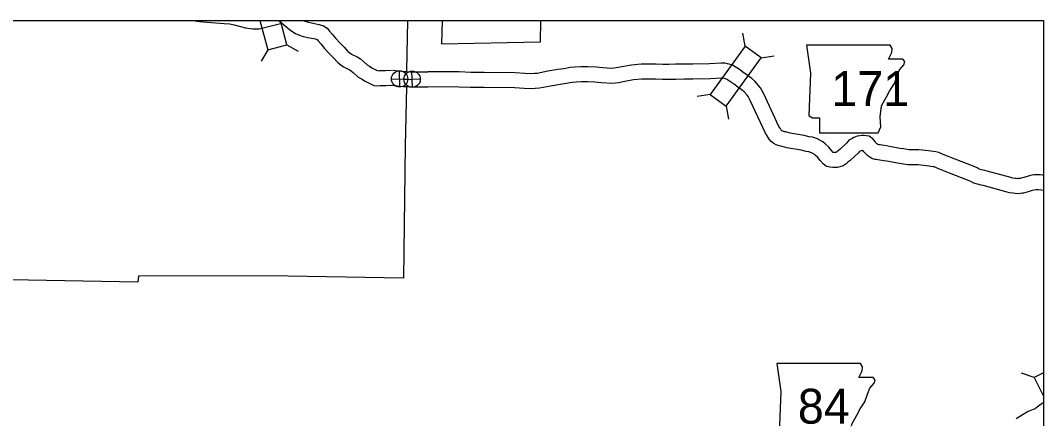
# Model space of a CAD drawing. Extents: x 1373862 to 1377080, y 1164775 to 1170415.
# Drawn here: x 1374409.6 to 1374613.9, y 1170309.3 to 1170388.8 of the extents above; entities that cross this region are included whole.
import ezdxf

# ---------------------------------------------------------------- set-up
doc = ezdxf.new("R2010")
doc.units = 0
doc.layers.add('1', color=7, linetype='Continuous')
doc.layers.add('Default', color=7, linetype='Continuous')

msp = doc.modelspace()

# ---------------------------------------------------------------- linework, layer by layer
at = {"layer": '1'}
msp.add_lwpolyline([(1373884.49, 1170388.77), (1374613.88, 1170388.77), (1374613.88, 1169861.94), (1373884.49, 1169861.94)], close=True, dxfattribs=at)
at = {"layer": 'Default'}
for p, q in [((1374554.29, 1170383.62), (1374553.87, 1170386.22)), ((1374459, 1170382.92), (1374457.68, 1170380.63)), ((1374462.83, 1170383.93), (1374465.11, 1170382.61)), ((1374557.5, 1170381.3), (1374560.11, 1170381.72)), ((1374485.38, 1170375.46), (1374485.3, 1170378.71)), ((1374487.88, 1170375.41), (1374487.8, 1170378.67)), ((1374483.71, 1170377.05), (1374486.97, 1170377.12)), ((1374486.21, 1170377), (1374489.47, 1170377.08)), ((1374547.34, 1170373.98), (1374544.73, 1170373.56)), ((1374550.55, 1170371.67), (1374550.97, 1170369.06)), ((1374612.02, 1170317.49), (1374609.51, 1170318.32)), ((1374613.88, 1170318.43), (1374612.02, 1170317.49)), ((1374612.02, 1170317.49), (1374613.88, 1170313.77))]:
    msp.add_line(p, q, dxfattribs=at)
for points in [[(1374443.92, 1170388.77), (1374444.08, 1170388.74), (1374445.42, 1170388.58), (1374447.72, 1170388.35), (1374450.32, 1170388.17), (1374451.45, 1170388.09), (1374452.33, 1170387.91), (1374453.55, 1170387.59), (1374454.54, 1170387.3), (1374455.98, 1170387.1)], [(1374457.45, 1170388.77), (1374459, 1170382.92), (1374462.83, 1170383.93), (1374461.55, 1170388.77)], [(1374461.16, 1170388.77), (1374461.49, 1170388.52), (1374462.4, 1170387.76), (1374463.44, 1170386.9), (1374464.58, 1170386.16), (1374465.37, 1170385.82), (1374466.11, 1170385.58), (1374467.38, 1170385.32), (1374468.53, 1170385.08), (1374468.83, 1170384.99), (1374468.85, 1170384.97), (1374469.07, 1170384.72), (1374469.58, 1170384.08), (1374470.35, 1170383.19), (1374471.3, 1170382.2), (1374472.06, 1170381.39), (1374472.99, 1170380.36), (1374473.61, 1170379.89), (1374474.15, 1170379.5), (1374475.45, 1170378.84), (1374475.75, 1170378.67), (1374476.07, 1170378.38), (1374477.07, 1170377.43), (1374477.84, 1170377.03), (1374478.34, 1170376.73), (1374479.42, 1170376.15), (1374480.18, 1170375.81), (1374480.99, 1170375.73), (1374481.45, 1170375.77), (1374482.61, 1170375.79), (1374483.79, 1170375.82)], [(1374466.1, 1170388.77), (1374466.42, 1170388.64), (1374466.89, 1170388.49), (1374467.99, 1170388.26), (1374469.3, 1170387.99), (1374470.17, 1170387.71), (1374470.87, 1170387.22), (1374471.37, 1170386.64), (1374471.89, 1170386), (1374472.57, 1170385.22), (1374473.48, 1170384.26), (1374474.26, 1170383.42), (1374475.03, 1170382.58), (1374475.41, 1170382.3), (1374475.72, 1170382.07), (1374476.89, 1170381.48), (1374477.52, 1170381.11), (1374478.1, 1170380.59), (1374478.84, 1170379.89), (1374479.3, 1170379.64), (1374479.81, 1170379.34), (1374480.75, 1170378.84), (1374480.96, 1170378.75), (1374481.02, 1170378.74), (1374481.31, 1170378.76), (1374482.55, 1170378.79), (1374483.73, 1170378.81)], [(1374486.93, 1170388.77), (1374486.74, 1170378.69)], [(1374493.81, 1170388.77), (1374493.69, 1170384.11), (1374513.44, 1170384.47), (1374513.55, 1170388.77)], [(1374455.98, 1170387.1), (1374455.98, 1170387.1), (1374456.67, 1170387.08), (1374457.32, 1170387.12), (1374458.6, 1170387.4), (1374460.25, 1170387.84), (1374461.85, 1170388.23)], [(1374483.92, 1170378.81), (1374485.11, 1170378.68), (1374486.29, 1170378.59), (1374486.79, 1170378.57)], [(1374486.87, 1170378.57), (1374487.42, 1170378.54), (1374488.49, 1170378.54), (1374489.72, 1170378.54), (1374491, 1170378.53)], [(1374522.88, 1170379.52), (1374521.48, 1170379.51), (1374520.31, 1170379.43), (1374519.41, 1170379.35), (1374518.14, 1170379.14), (1374516.92, 1170378.96), (1374514.95, 1170378.63), (1374512.81, 1170378.2), (1374512.26, 1170378.15), (1374511.7, 1170378.14), (1374510.32, 1170378.19), (1374508.38, 1170378.32), (1374502.19, 1170378.37), (1374500.66, 1170378.35), (1374499.55, 1170378.4), (1374497.24, 1170378.48), (1374490.99, 1170378.53)], [(1374596.23, 1170361.06), (1374594.19, 1170361.89), (1374593.68, 1170362.08), (1374592.98, 1170362.4), (1374592.41, 1170362.53), (1374590.9, 1170362.73), (1374588.98, 1170362.93), (1374587.01, 1170362.95), (1374585.95, 1170363.1), (1374585.2, 1170363.22), (1374584.19, 1170363.41), (1374583.11, 1170363.6), (1374582.5, 1170363.71), (1374581.68, 1170363.85), (1374581.27, 1170363.91), (1374581.04, 1170363.95), (1374580.84, 1170363.98), (1374580.8, 1170363.99), (1374580.77, 1170364.02), (1374580.63, 1170364.14), (1374580.48, 1170364.29), (1374580.37, 1170364.4), (1374580.25, 1170364.62), (1374579.83, 1170365.1), (1374579.09, 1170365.65), (1374578.57, 1170365.74), (1374578.07, 1170365.78), (1374577.66, 1170365.77), (1374577.18, 1170365.72), (1374576.7, 1170365.67), (1374576.37, 1170365.53), (1374576.04, 1170365.42), (1374575.66, 1170365.2), (1374575, 1170364.84), (1374574.64, 1170364.31), (1374573.31, 1170363.07), (1374572.93, 1170362.79), (1374572.62, 1170362.52), (1374572.55, 1170362.47), (1374572.43, 1170362.43), (1374572.3, 1170362.4), (1374572.11, 1170362.39), (1374571.94, 1170362.38), (1374571.91, 1170362.39), (1374571.58, 1170362.77), (1374571.01, 1170363.44), (1374570.28, 1170364.13), (1374569.79, 1170364.54), (1374568.77, 1170365.12), (1374567.73, 1170365.45), (1374567.08, 1170365.55), (1374566.12, 1170365.78), (1374563.27, 1170366.28), (1374562.42, 1170366.51), (1374562.19, 1170366.56), (1374561.95, 1170366.62), (1374561.71, 1170366.7), (1374561.65, 1170366.73), (1374561.59, 1170366.78), (1374561.5, 1170366.88), (1374561.28, 1170367.23), (1374561.06, 1170367.62), (1374558.04, 1170374.11), (1374557.66, 1170374.82), (1374557.36, 1170375.33), (1374556.99, 1170375.76), (1374556.26, 1170376.66), (1374555.63, 1170377.17), (1374554.98, 1170377.63), (1374554.69, 1170377.84), (1374553.88, 1170378.44), (1374553.43, 1170378.76), (1374553, 1170379.08), (1374552.64, 1170379.29), (1374552.3, 1170379.51), (1374551.8, 1170379.82), (1374551.56, 1170379.89), (1374551.13, 1170380.04), (1374550.79, 1170380.1), (1374550.33, 1170380.22), (1374549.52, 1170380.25), (1374547.22, 1170380.1), (1374543.86, 1170380.04), (1374542.11, 1170380.03), (1374540.43, 1170380.01), (1374539.05, 1170379.97), (1374537.89, 1170380), (1374536.57, 1170380.03), (1374535.37, 1170380.05), (1374533.57, 1170380.02), (1374531.61, 1170379.86), (1374530.09, 1170379.58), (1374528.55, 1170379.28), (1374527.63, 1170379.17), (1374525.91, 1170379.31), (1374524.55, 1170379.46), (1374522.94, 1170379.52)], [(1374522.89, 1170376.52), (1374521.59, 1170376.51), (1374520.55, 1170376.44), (1374519.77, 1170376.37), (1374518.6, 1170376.18), (1374517.39, 1170376), (1374515.49, 1170375.68), (1374513.24, 1170375.22), (1374512.41, 1170375.15), (1374511.67, 1170375.14), (1374510.17, 1170375.19), (1374508.27, 1170375.32), (1374502.2, 1170375.37), (1374500.61, 1170375.35), (1374499.44, 1170375.4), (1374497.17, 1170375.48), (1374490.97, 1170375.53)], [(1374595.1, 1170358.28), (1374593.1, 1170359.09), (1374592.53, 1170359.31), (1374592.02, 1170359.54), (1374591.88, 1170359.57), (1374590.54, 1170359.75), (1374588.81, 1170359.93), (1374586.78, 1170359.95), (1374585.51, 1170360.14), (1374584.7, 1170360.26), (1374583.65, 1170360.45), (1374582.58, 1170360.64), (1374581.97, 1170360.76), (1374581.22, 1170360.89), (1374580.77, 1170360.95), (1374580.56, 1170360.99), (1374580.23, 1170361.03), (1374579.83, 1170361.15), (1374579.59, 1170361.22), (1374579.19, 1170361.44), (1374578.82, 1170361.74), (1374578.6, 1170361.94), (1374578.36, 1170362.17), (1374577.93, 1170362.62), (1374577.84, 1170362.77), (1374577.49, 1170362.74), (1374577.47, 1170362.74), (1374577.26, 1170362.66), (1374577.11, 1170362.58), (1374577.07, 1170362.56), (1374576.92, 1170362.34), (1374575.23, 1170360.76), (1374574.82, 1170360.46), (1374574.47, 1170360.15), (1374573.91, 1170359.76), (1374573.24, 1170359.54), (1374572.77, 1170359.43), (1374572.28, 1170359.39), (1374571.83, 1170359.38), (1374571.22, 1170359.44), (1374570.57, 1170359.63), (1374569.86, 1170360.16), (1374569.3, 1170360.81), (1374568.83, 1170361.37), (1374568.28, 1170361.89), (1374568.07, 1170362.06), (1374567.55, 1170362.36), (1374567.04, 1170362.52), (1374566.5, 1170362.61), (1374565.51, 1170362.84), (1374562.63, 1170363.35), (1374561.7, 1170363.59), (1374561.46, 1170363.65), (1374561.1, 1170363.75), (1374560.53, 1170363.93), (1374560.02, 1170364.2), (1374559.53, 1170364.58), (1374559.1, 1170365.07), (1374558.7, 1170365.7), (1374558.39, 1170366.27), (1374555.35, 1170372.76), (1374555.04, 1170373.35), (1374554.9, 1170373.59), (1374554.69, 1170373.84), (1374554.14, 1170374.52), (1374553.81, 1170374.78), (1374553.25, 1170375.18), (1374552.93, 1170375.4), (1374552.1, 1170376.02), (1374551.68, 1170376.33), (1374551.34, 1170376.57), (1374551.06, 1170376.74), (1374550.71, 1170376.97), (1374550.55, 1170377.07), (1374550.36, 1170377.13), (1374550.14, 1170377.17), (1374549.89, 1170377.24), (1374549.56, 1170377.25), (1374547.35, 1170377.1), (1374543.9, 1170377.04), (1374542.14, 1170377.03), (1374540.5, 1170377.01), (1374539.04, 1170376.97), (1374537.82, 1170377), (1374536.51, 1170377.03), (1374535.36, 1170377.05), (1374533.72, 1170377.03), (1374532.01, 1170376.88), (1374530.65, 1170376.63), (1374529.01, 1170376.31), (1374527.68, 1170376.16), (1374525.63, 1170376.33), (1374524.34, 1170376.47), (1374522.83, 1170376.52)], [(1374486.68, 1170375.47), (1374486.46, 1170363.78), (1374486.09, 1170337.31), (1374459.22, 1170337.74), (1374433.2, 1170337.7), (1374433.11, 1170336.48), (1374407.56, 1170336.94)], [(1374483.61, 1170375.82), (1374484.84, 1170375.7), (1374486.1, 1170375.6), (1374486.74, 1170375.57)], [(1374486.66, 1170375.57), (1374487.34, 1170375.54), (1374488.49, 1170375.54), (1374489.72, 1170375.54), (1374490.96, 1170375.53)], [(1374613.88, 1170357.83), (1374613.76, 1170357.85), (1374613.2, 1170357.92), (1374612.6, 1170357.97), (1374611.95, 1170357.91), (1374611.28, 1170357.79), (1374610.6, 1170357.61), (1374609.97, 1170357.42), (1374609.61, 1170357.31), (1374609.31, 1170357.24), (1374609.25, 1170357.23), (1374608.87, 1170357.19), (1374608.72, 1170357.17), (1374608.5, 1170357.19), (1374608.24, 1170357.23), (1374607.75, 1170357.3), (1374607.38, 1170357.4), (1374602.64, 1170358.68), (1374602.17, 1170358.81), (1374601.5, 1170358.96), (1374601.05, 1170359.1), (1374600.61, 1170359.31), (1374599.83, 1170359.66), (1374596.21, 1170361.07)], [(1374613.88, 1170354.81), (1374613.39, 1170354.87), (1374612.89, 1170354.93), (1374612.61, 1170354.96), (1374612.34, 1170354.93), (1374611.92, 1170354.86), (1374611.42, 1170354.73), (1374610.83, 1170354.55), (1374610.38, 1170354.41), (1374609.9, 1170354.3), (1374609.68, 1170354.26), (1374609.19, 1170354.21), (1374608.74, 1170354.16), (1374608.19, 1170354.21), (1374607.81, 1170354.26), (1374607.12, 1170354.37), (1374606.6, 1170354.51), (1374601.86, 1170355.78), (1374601.44, 1170355.9), (1374600.72, 1170356.06), (1374599.97, 1170356.29), (1374599.36, 1170356.58), (1374598.67, 1170356.89), (1374595.12, 1170358.28)], [(1374613.88, 1170312.45), (1374613.82, 1170312.41), (1374613.13, 1170311.92), (1374612.61, 1170311.52), (1374612.28, 1170311.25), (1374612.21, 1170311.19), (1374611.82, 1170311.07), (1374610.79, 1170310.66), (1374610.17, 1170310.26), (1374609.8, 1170310.06), (1374608.39, 1170309.18)]]:
    msp.add_lwpolyline(points, dxfattribs=at)
for points in [[(1374554.29, 1170383.62), (1374547.34, 1170373.98), (1374550.55, 1170371.67), (1374557.5, 1170381.3)], [(1374566.54, 1170383.83), (1374567.38, 1170378.24), (1374567.01, 1170369.78), (1374567.75, 1170369.31), (1374569.15, 1170369.31), (1374569.15, 1170366.33), (1374580.87, 1170366.33), (1374581.43, 1170367.54), (1374581.25, 1170369.5), (1374581.52, 1170371.73), (1374582.55, 1170373.5), (1374583.2, 1170374.8), (1374584.13, 1170376.2), (1374584.69, 1170377.69), (1374585.15, 1170378.89), (1374585.99, 1170379.92), (1374586.18, 1170380.57), (1374585.8, 1170381.03), (1374582.92, 1170381.03), (1374583.57, 1170382.34), (1374583.66, 1170383.18), (1374583.28, 1170383.82)], [(1374560.62, 1170320.26), (1374561.46, 1170314.68), (1374561.09, 1170306.21), (1374561.83, 1170305.74), (1374563.23, 1170305.74), (1374563.23, 1170302.77), (1374574.95, 1170302.77), (1374575.51, 1170303.98), (1374575.33, 1170305.93), (1374575.6, 1170308.16), (1374576.63, 1170309.93), (1374577.28, 1170311.23), (1374578.21, 1170312.63), (1374578.77, 1170314.12), (1374579.23, 1170315.33), (1374580.07, 1170316.35), (1374580.26, 1170317), (1374579.88, 1170317.47), (1374577, 1170317.47), (1374577.65, 1170318.77), (1374577.74, 1170319.61), (1374577.36, 1170320.25)]]:
    msp.add_lwpolyline(points, close=True, dxfattribs=at)
for centre in [(1374485.34, 1170377.09), (1374487.84, 1170377.04)]:
    msp.add_circle(centre, 1.63, dxfattribs=at)

# ---------------------------------------------------------------- texts
for s, p in [('171', (1374571.51, 1170371.68)), ('84', (1374564.83, 1170308.25))]:
    msp.add_text(s, height=6.97, dxfattribs=at).set_placement(p)

doc.saveas('drawing.dxf')
